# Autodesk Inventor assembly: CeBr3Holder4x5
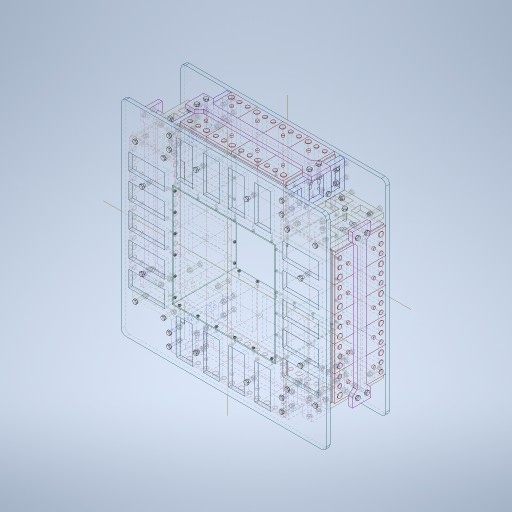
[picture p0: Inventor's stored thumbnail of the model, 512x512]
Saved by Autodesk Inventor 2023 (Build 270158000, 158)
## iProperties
Created: 2023-10
Part Number: CeBr3Holder4x5
Document SubType Name: Assembly
Designer: tornqvih
Mass: 42931.8 g
Surface Area: 23628.1 cm^2
Volume: 15849 cm^3
Density: 2.7088 g/cm^3
Author: tornqvih
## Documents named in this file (21)
- \\Mac\Home\Documents\chalmers\Inventor2023\CeBr3Holder4x5\CeBr3Holder4x5.iam
- \\Mac\Home\Documents\chalmers\Inventor2023\CeBr3Holder4x5\FrontPlate.ipt
- \\Mac\Home\Documents\chalmers\Inventor2023\CeBr3Holder4x5\ShieldTop.ipt
- \\Mac\Home\Documents\chalmers\Inventor2023\CeBr3Holder4x5\ShieldLeft.ipt
- \\Mac\Home\Documents\chalmers\Inventor2023\CeBr3Holder4x5\SupportHorizontal.ipt
- \\Mac\Home\Documents\chalmers\Inventor2023\CeBr3Holder4x5\SupportVertical.ipt
- \\Mac\Home\Documents\chalmers\Inventor2023\CeBr3Holder4x5\BarHorizontal.ipt
- \\Mac\Home\Documents\chalmers\Inventor2023\CeBr3Holder4x5\BarVertical.ipt
- \\Mac\Home\Documents\chalmers\Inventor2023\CeBr3Holder4x5\CeBr3.ipt
- \\Mac\Home\Documents\Inventor\Content Center Files\R2023\en-US\AS 1110\AS 1110 - M5 x 25.ipt
- \\Mac\Home\Documents\Inventor\Content Center Files\R2023\en-US\AS 1112 (2)\AS 1112 - M5  Type 5.ipt
- \\Mac\Home\Documents\Inventor\Content Center Files\R2023\en-US\AS 1427(05)\AS 1427 - M2.5 x 8(5) II.ipt
- \\Mac\Home\Documents\Inventor\Content Center Files\R2023\en-US\AS 1110\AS 1110 - M5 x 35.ipt
- \\Mac\Home\Documents\Inventor\Content Center Files\R2023\en-US\AS 1110\AS 1110 - M5 x 40.ipt
- \\Mac\Home\Documents\Inventor\Content Center Files\R2023\en-US\ANSI B18.2.4.2M\ANSI B18.2.4.2M - M5x0.8 - 8.ipt
- \\Mac\Home\Documents\chalmers\Inventor2023\CeBr3Holder4x5\Mount.ipt
- \\Mac\Home\Documents\chalmers\Inventor2023\CeBr3Holder4x5\PressTopBottom.ipt
- \\Mac\Home\Documents\chalmers\Inventor2023\CeBr3Holder4x5\PressRightLeft.ipt
- \\Mac\Home\Documents\chalmers\Inventor2023\CeBr3Holder4x5\PressSide.ipt
- \\Mac\Home\Documents\Inventor\Content Center Files\R2023\en-US\AS 1474(1)\AS 1474 - M5(1).ipt
- \\Mac\Home\Documents\Inventor\Content Center Files\R2023\en-US\AS 1110\AS 1110 - M5 x 20.ipt
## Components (239 placed, 36 different names)
1. FrontPlate
2. BackPlate
3. ShieldTop
4. ShieldBottom
5. ShieldLeft
6. ShieldRight
7. SupportHorizontalTR
8. SupportHorizontalTL
9. SupportHorizontalBL
10. SupportHorizontalBR
11. SupportVerticalTR
12. SupportVerticalTL
13. SupportVerticalBL
14. SupportVerticalBR
15. BarHorizontalTop — Mate:129, Mate:131, Flush:129
16. BarHorizontalBottom — Mate:132, Mate:133, Flush:130
17. BarVerticalRight — Mate:134, Mate:135, Flush:131
18. BarVertical:2 — Mate:136, Mate:137, Flush:132
19. CeBr3:1 — Mate:138, Mate:139, Mate:140, Mate:143, Mate:151
20. CeBr3:2 — Mate:141, Mate:142, Mate:143, Mate:146, Mate:154
21. CeBr3:3 — Mate:144, Mate:145, Mate:146, Mate:149, Mate:157
22. CeBr3:4 — Mate:147, Mate:148, Mate:149, Mate:160, Mate:269
23. CeBr3:5 — Mate:150, Mate:151, Mate:152, Mate:155, Mate:257, Mate:277
24. CeBr3:6 — Mate:153, Mate:154, Mate:155, Mate:158
25. CeBr3:7 — Mate:156, Mate:157, Mate:158, Mate:161
26. CeBr3:8 — Mate:159, Mate:160, Mate:161
27. CeBr3:9 — Mate:162, Mate:163, Mate:164, Mate:167, Mate:175
28. CeBr3:10 — Mate:165, Mate:166, Mate:167, Mate:170, Mate:178
29. CeBr3:11 — Mate:168, Mate:169, Mate:170, Mate:173, Mate:181
30. CeBr3:12 — Mate:171, Mate:172, Mate:173, Mate:184, Mate:272
31. CeBr3:13 — Mate:174, Mate:175, Mate:176, Mate:179, Mate:260
32. CeBr3:14 — Mate:177, Mate:178, Mate:179, Mate:182
33. CeBr3:15 — Mate:180, Mate:181, Mate:182, Mate:185
34. CeBr3:16 — Mate:183, Mate:184, Mate:185
35. CeBr3:17 — Mate:186, Mate:187, Mate:188, Mate:191, Mate:202
36. CeBr3:18 — Mate:189, Mate:190, Mate:191, Mate:194, Mate:205
37. CeBr3:19 — Mate:192, Mate:193, Mate:194, Mate:197, Mate:208
38. CeBr3:20 — Mate:195, Mate:196, Mate:197, Mate:200, Mate:211
39. CeBr3:21 — Mate:198, Mate:199, Mate:200, Mate:214, Mate:278
40. CeBr3:22 — Mate:201, Mate:202, Mate:203, Mate:206, Mate:266
41. CeBr3:23 — Mate:204, Mate:205, Mate:206, Mate:209
42. CeBr3:24 — Mate:207, Mate:208, Mate:209, Mate:212
43. CeBr3:25 — Mate:210, Mate:211, Mate:212, Mate:215
44. CeBr3:26 — Mate:213, Mate:214, Mate:215
45. CeBr3:27 — Mate:216, Mate:217, Mate:218, Mate:221, Mate:232
46. CeBr3:28 — Mate:219, Mate:220, Mate:221, Mate:224, Mate:235
47. CeBr3:29 — Mate:222, Mate:223, Mate:224, Mate:227, Mate:238
48. CeBr3:30 — Mate:225, Mate:226, Mate:227, Mate:230, Mate:241
49. CeBr3:31 — Mate:228, Mate:229, Mate:230, Mate:244, Mate:275
50. CeBr3:32 — Mate:231, Mate:232, Mate:233, Mate:236, Mate:263
51. CeBr3:33 — Mate:234, Mate:235, Mate:236, Mate:239
52. CeBr3:34 — Mate:237, Mate:238, Mate:239, Mate:242
53. CeBr3:35 — Mate:240, Mate:241, Mate:242, Mate:245
54. CeBr3:36 — Mate:243, Mate:244, Mate:245
55. AS 1110 - Metric M5 x 25:1
56. AS 1110 - Metric M5 x 25:2
57. AS 1110 - Metric M5 x 25:3
58. AS 1110 - Metric M5 x 25:4
59. AS 1110 - Metric M5 x 25:5
60. AS 1110 - Metric M5 x 25:6
61. AS 1110 - Metric M5 x 25:7
62. AS 1110 - Metric M5 x 25:8
63. AS 1110 - Metric M5 x 25:9
64. AS 1110 - Metric M5 x 25:10
65. AS 1110 - Metric M5 x 25:11
66. AS 1110 - Metric M5 x 25:12
67. AS 1110 - Metric M5 x 25:13
68. AS 1110 - Metric M5 x 25:14
69. AS 1110 - Metric M5 x 25:15
70. AS 1110 - Metric M5 x 25:16
71. AS 1110 - Metric M5 x 25:17
72. AS 1110 - Metric M5 x 25:18
73. AS 1110 - Metric M5 x 25:19
74. AS 1110 - Metric M5 x 25:20
75. AS 1110 - Metric M5 x 25:21
76. AS 1110 - Metric M5 x 25:22
77. AS 1110 - Metric M5 x 25:23
78. AS 1110 - Metric M5 x 25:24
79. AS 1110 - Metric M5 x 25:25
80. AS 1110 - Metric M5 x 25:26
81. AS 1110 - Metric M5 x 25:27
82. AS 1110 - Metric M5 x 25:28
83. AS 1110 - Metric M5 x 25:29
84. AS 1110 - Metric M5 x 25:30
85. AS 1110 - Metric M5 x 25:31
86. AS 1110 - Metric M5 x 25:32
87. AS 1112 (2) - Metric M5  Type 5:1
88. AS 1112 (2) - Metric M5  Type 5:2
89. AS 1112 (2) - Metric M5  Type 5:3
90. AS 1112 (2) - Metric M5  Type 5:4
91. AS 1112 (2) - Metric M5  Type 5:5
92. AS 1112 (2) - Metric M5  Type 5:6
93. AS 1112 (2) - Metric M5  Type 5:7
94. AS 1112 (2) - Metric M5  Type 5:8
95. AS 1112 (2) - Metric M5  Type 5:9
96. AS 1112 (2) - Metric M5  Type 5:10
97. AS 1112 (2) - Metric M5  Type 5:11
98. AS 1112 (2) - Metric M5  Type 5:12
99. AS 1112 (2) - Metric M5  Type 5:13
100. AS 1112 (2) - Metric M5  Type 5:14
101. AS 1112 (2) - Metric M5  Type 5:15
102. AS 1112 (2) - Metric M5  Type 5:16
103. AS 1112 (2) - Metric M5  Type 5:17
104. AS 1112 (2) - Metric M5  Type 5:18
105. AS 1112 (2) - Metric M5  Type 5:19
106. AS 1112 (2) - Metric M5  Type 5:20
107. AS 1112 (2) - Metric M5  Type 5:21
108. AS 1112 (2) - Metric M5  Type 5:22
109. AS 1112 (2) - Metric M5  Type 5:23
110. AS 1112 (2) - Metric M5  Type 5:24
111. AS 1112 (2) - Metric M5  Type 5:25
112. AS 1112 (2) - Metric M5  Type 5:26
113. AS 1112 (2) - Metric M5  Type 5:27
114. AS 1112 (2) - Metric M5  Type 5:28
115. AS 1112 (2) - Metric M5  Type 5:29
116. AS 1112 (2) - Metric M5  Type 5:30
117. AS 1112 (2) - Metric M5  Type 5:31
118. AS 1112 (2) - Metric M5  Type 5:32
119. AS 1427 H - Metric M2.5 x 8:1
120. AS 1427 H - Metric M2.5 x 8:2
121. AS 1427 H - Metric M2.5 x 8:3
122. AS 1427 H - Metric M2.5 x 8:4
123. AS 1427 H - Metric M2.5 x 8:5
124. AS 1427 H - Metric M2.5 x 8:6
125. AS 1427 H - Metric M2.5 x 8:7
126. AS 1427 H - Metric M2.5 x 8:8
127. AS 1427 H - Metric M2.5 x 8:9
128. AS 1427 H - Metric M2.5 x 8:10
129. AS 1427 H - Metric M2.5 x 8:11
130. AS 1427 H - Metric M2.5 x 8:12
131. AS 1427 H - Metric M2.5 x 8:13
132. AS 1427 H - Metric M2.5 x 8:14
133. AS 1427 H - Metric M2.5 x 8:15
134. AS 1427 H - Metric M2.5 x 8:16
135. AS 1427 H - Metric M2.5 x 8:17
136. AS 1427 H - Metric M2.5 x 8:18
137. AS 1427 H - Metric M2.5 x 8:19
138. AS 1427 H - Metric M2.5 x 8:20
139. AS 1427 H - Metric M2.5 x 8:21
140. AS 1427 H - Metric M2.5 x 8:22
141. AS 1427 H - Metric M2.5 x 8:23
142. AS 1427 H - Metric M2.5 x 8:24
143. AS 1427 H - Metric M2.5 x 8:25
144. AS 1427 H - Metric M2.5 x 8:26
145. AS 1427 H - Metric M2.5 x 8:27
146. AS 1427 H - Metric M2.5 x 8:28
147. AS 1427 H - Metric M2.5 x 8:29
148. AS 1427 H - Metric M2.5 x 8:30
149. AS 1427 H - Metric M2.5 x 8:31
150. AS 1427 H - Metric M2.5 x 8:32
151. AS 1427 H - Metric M2.5 x 8:33
152. AS 1427 H - Metric M2.5 x 8:34
153. AS 1427 H - Metric M2.5 x 8:35
154. AS 1427 H - Metric M2.5 x 8:36
155. AS 1427 H - Metric M2.5 x 8:37
156. AS 1427 H - Metric M2.5 x 8:38
157. AS 1427 H - Metric M2.5 x 8:39
158. AS 1427 H - Metric M2.5 x 8:40
159. AS 1427 H - Metric M2.5 x 8:41
160. AS 1427 H - Metric M2.5 x 8:42
161. AS 1427 H - Metric M2.5 x 8:43
162. AS 1427 H - Metric M2.5 x 8:44
163. AS 1427 H - Metric M2.5 x 8:45
164. AS 1427 H - Metric M2.5 x 8:46
165. AS 1427 H - Metric M2.5 x 8:47
166. AS 1427 H - Metric M2.5 x 8:48
167. AS 1110 - Metric M5 x 35:25
168. AS 1110 - Metric M5 x 35:3
169. AS 1110 - Metric M5 x 35:5
170. AS 1110 - Metric M5 x 35:6
171. AS 1110 - Metric M5 x 35:7
172. AS 1110 - Metric M5 x 35:9
173. AS 1110 - Metric M5 x 35:11
174. AS 1110 - Metric M5 x 35:12
175. AS 1110 - Metric M5 x 35:13
176. AS 1110 - Metric M5 x 35:15
177. AS 1110 - Metric M5 x 35:16
178. AS 1110 - Metric M5 x 35:18
179. AS 1110 - Metric M5 x 40:1
180. AS 1110 - Metric M5 x 40:3
181. AS 1110 - Metric M5 x 40:4
182. AS 1110 - Metric M5 x 40:6
183. ANSI B18.2.4.2M M5x0.8:1
184. ANSI B18.2.4.2M M5x0.8:3
185. ANSI B18.2.4.2M M5x0.8:4
186. ANSI B18.2.4.2M M5x0.8:6
187. ANSI B18.2.4.2M M5x0.8:7
188. ANSI B18.2.4.2M M5x0.8:9
189. ANSI B18.2.4.2M M5x0.8:10
190. ANSI B18.2.4.2M M5x0.8:12
191. ANSI B18.2.4.2M M5x0.8:13
192. ANSI B18.2.4.2M M5x0.8:15
193. ANSI B18.2.4.2M M5x0.8:16
194. ANSI B18.2.4.2M M5x0.8:18
195. ANSI B18.2.4.2M M5x0.8:19
196. ANSI B18.2.4.2M M5x0.8:21
197. ANSI B18.2.4.2M M5x0.8:22
198. ANSI B18.2.4.2M M5x0.8:24
199. Mount:1 — Mate:255
200. PressTop — Mate:256, Mate:257, Mate:258, Mate:280, Mate:282
201. PressBottom — Mate:259, Mate:260, Mate:261, Mate:288, Mate:290
202. PressRight — Mate:262, Mate:263, Mate:264, Mate:284, Mate:286
203. PressLef — Mate:265, Mate:266, Mate:267, Mate:292, Mate:294
204. PressSideTop — Mate:268, Mate:269, Mate:270, Mate:274, Mate:296, Mate:298
205. PressSideBottom — Mate:271, Mate:272, Mate:273, Mate:304, Mate:306
206. PressSideRight — Mate:274, Mate:275, Mate:276, Mate:300, Mate:302
207. PressSideLeft — Mate:277, Mate:278, Mate:279, Mate:308, Mate:310
208. AS 1474 - Metric M5:1
209. AS 1474 - Metric M5:2
210. AS 1474 - Metric M5:3
211. AS 1474 - Metric M5:4
212. AS 1474 - Metric M5:5
213. AS 1474 - Metric M5:6
214. AS 1474 - Metric M5:7
215. AS 1474 - Metric M5:8
216. AS 1474 - Metric M5:9
217. AS 1474 - Metric M5:10
218. AS 1474 - Metric M5:11
219. AS 1474 - Metric M5:12
220. AS 1474 - Metric M5:13
221. AS 1474 - Metric M5:14
222. AS 1474 - Metric M5:15
223. AS 1474 - Metric M5:16
224. AS 1110 - Metric M5 x 20:33 — Mate:280, Mate:281
225. AS 1110 - Metric M5 x 20:2 — Mate:282, Mate:283
226. AS 1110 - Metric M5 x 20:3 — Mate:284, Mate:285
227. AS 1110 - Metric M5 x 20:4 — Mate:286, Mate:287
228. AS 1110 - Metric M5 x 20:5 — Mate:288, Mate:289
229. AS 1110 - Metric M5 x 20:6 — Mate:290, Mate:291
230. AS 1110 - Metric M5 x 20:7 — Mate:292, Mate:293
231. AS 1110 - Metric M5 x 20:8 — Mate:294, Mate:295
232. AS 1110 - Metric M5 x 20:9 — Mate:296, Mate:297
233. AS 1110 - Metric M5 x 20:10 — Mate:298, Mate:299
234. AS 1110 - Metric M5 x 20:11 — Mate:300, Mate:301
235. AS 1110 - Metric M5 x 20:12 — Mate:302, Mate:303
236. AS 1110 - Metric M5 x 20:13 — Mate:304, Mate:305
237. AS 1110 - Metric M5 x 20:14 — Mate:306, Mate:307
238. AS 1110 - Metric M5 x 20:15 — Mate:308, Mate:309
239. AS 1110 - Metric M5 x 20:16 — Mate:310, Mate:311
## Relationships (177: Mate 173, Flush 4)
- Mate:129: BarHorizontalTop
- Mate:131: BarHorizontalTop
- Flush:129: BarHorizontalTop
- Mate:132: BarHorizontalBottom
- Mate:133: BarHorizontalBottom
- Flush:130: BarHorizontalBottom
- Mate:134: BarVerticalRight
- Mate:135: BarVerticalRight
- Flush:131: BarVerticalRight
- Mate:136: BarVertical:2
- Mate:137: BarVertical:2
- Flush:132: BarVertical:2
- Mate:138: CeBr3:1
- Mate:139: CeBr3:1
- Mate:140: CeBr3:1
- Mate:141: CeBr3:2
- Mate:142: CeBr3:2
- Mate:143: CeBr3:1 ↔ CeBr3:2
- Mate:144: CeBr3:3
- Mate:145: CeBr3:3
- Mate:146: CeBr3:2 ↔ CeBr3:3
- Mate:147: CeBr3:4
- Mate:148: CeBr3:4
- Mate:149: CeBr3:3 ↔ CeBr3:4
- Mate:150: CeBr3:5
- Mate:151: CeBr3:1 ↔ CeBr3:5
- Mate:152: CeBr3:5
- Mate:153: CeBr3:6
- Mate:154: CeBr3:2 ↔ CeBr3:6
- Mate:155: CeBr3:5 ↔ CeBr3:6
- Mate:156: CeBr3:7
- Mate:157: CeBr3:3 ↔ CeBr3:7
- Mate:158: CeBr3:6 ↔ CeBr3:7
- Mate:159: CeBr3:8
- Mate:160: CeBr3:4 ↔ CeBr3:8
- Mate:161: CeBr3:7 ↔ CeBr3:8
- Mate:162: CeBr3:9
- Mate:163: CeBr3:9
- Mate:164: CeBr3:9
- Mate:165: CeBr3:10
- Mate:166: CeBr3:10
- Mate:167: CeBr3:9 ↔ CeBr3:10
- Mate:168: CeBr3:11
- Mate:169: CeBr3:11
- Mate:170: CeBr3:10 ↔ CeBr3:11
- Mate:171: CeBr3:12
- Mate:172: CeBr3:12
- Mate:173: CeBr3:11 ↔ CeBr3:12
- Mate:174: CeBr3:13
- Mate:175: CeBr3:9 ↔ CeBr3:13
- Mate:176: CeBr3:13
- Mate:177: CeBr3:14
- Mate:178: CeBr3:10 ↔ CeBr3:14
- Mate:179: CeBr3:13 ↔ CeBr3:14
- Mate:180: CeBr3:15
- Mate:181: CeBr3:11 ↔ CeBr3:15
- Mate:182: CeBr3:14 ↔ CeBr3:15
- Mate:183: CeBr3:16
- Mate:184: CeBr3:12 ↔ CeBr3:16
- Mate:185: CeBr3:15 ↔ CeBr3:16
- Mate:186: CeBr3:17
- Mate:187: CeBr3:17
- Mate:188: CeBr3:17
- Mate:189: CeBr3:18
- Mate:190: CeBr3:18
- Mate:191: CeBr3:17 ↔ CeBr3:18
- Mate:192: CeBr3:19
- Mate:193: CeBr3:19
- Mate:194: CeBr3:18 ↔ CeBr3:19
- Mate:195: CeBr3:20
- Mate:196: CeBr3:20
- Mate:197: CeBr3:19 ↔ CeBr3:20
- Mate:198: CeBr3:21
- Mate:199: CeBr3:21
- Mate:200: CeBr3:20 ↔ CeBr3:21
- Mate:201: CeBr3:22
- Mate:202: CeBr3:17 ↔ CeBr3:22
- Mate:203: CeBr3:22
- Mate:204: CeBr3:23
- Mate:205: CeBr3:18 ↔ CeBr3:23
- Mate:206: CeBr3:22 ↔ CeBr3:23
- Mate:207: CeBr3:24
- Mate:208: CeBr3:19 ↔ CeBr3:24
- Mate:209: CeBr3:23 ↔ CeBr3:24
- Mate:210: CeBr3:25
- Mate:211: CeBr3:20 ↔ CeBr3:25
- Mate:212: CeBr3:24 ↔ CeBr3:25
- Mate:213: CeBr3:26
- Mate:214: CeBr3:21 ↔ CeBr3:26
- Mate:215: CeBr3:25 ↔ CeBr3:26
- Mate:216: CeBr3:27
- Mate:217: CeBr3:27
- Mate:218: CeBr3:27
- Mate:219: CeBr3:28
- Mate:220: CeBr3:28
- Mate:221: CeBr3:27 ↔ CeBr3:28
- Mate:222: CeBr3:29
- Mate:223: CeBr3:29
- Mate:224: CeBr3:28 ↔ CeBr3:29
- Mate:225: CeBr3:30
- Mate:226: CeBr3:30
- Mate:227: CeBr3:29 ↔ CeBr3:30
- Mate:228: CeBr3:31
- Mate:229: CeBr3:31
- Mate:230: CeBr3:30 ↔ CeBr3:31
- Mate:231: CeBr3:32
- Mate:232: CeBr3:27 ↔ CeBr3:32
- Mate:233: CeBr3:32
- Mate:234: CeBr3:33
- Mate:235: CeBr3:28 ↔ CeBr3:33
- Mate:236: CeBr3:32 ↔ CeBr3:33
- Mate:237: CeBr3:34
- Mate:238: CeBr3:29 ↔ CeBr3:34
- Mate:239: CeBr3:33 ↔ CeBr3:34
- Mate:240: CeBr3:35
- Mate:241: CeBr3:30 ↔ CeBr3:35
- Mate:242: CeBr3:34 ↔ CeBr3:35
- Mate:243: CeBr3:36
- Mate:244: CeBr3:31 ↔ CeBr3:36
- Mate:245: CeBr3:35 ↔ CeBr3:36
- Mate:255: Mount:1
- Mate:256: PressTop
- Mate:257: CeBr3:5 ↔ PressTop
- Mate:258: PressTop
- Mate:259: PressBottom
- Mate:260: CeBr3:13 ↔ PressBottom
- Mate:261: PressBottom
- Mate:262: PressRight
- Mate:263: CeBr3:32 ↔ PressRight
- Mate:264: PressRight
- Mate:265: PressLef
- Mate:266: CeBr3:22 ↔ PressLef
- Mate:267: PressLef
- Mate:268: PressSideTop
- Mate:269: CeBr3:4 ↔ PressSideTop
- Mate:270: PressSideTop
- Mate:271: PressSideBottom
- Mate:272: CeBr3:12 ↔ PressSideBottom
- Mate:273: PressSideBottom
- Mate:274: PressSideTop ↔ PressSideRight
- Mate:275: CeBr3:31 ↔ PressSideRight
- Mate:276: PressSideRight
- Mate:277: CeBr3:5 ↔ PressSideLeft
- Mate:278: CeBr3:21 ↔ PressSideLeft
- Mate:279: PressSideLeft
- Mate:280: PressTop ↔ AS 1110 - Metric M5 x 20:33
- Mate:281: AS 1110 - Metric M5 x 20:33
- Mate:282: PressTop ↔ AS 1110 - Metric M5 x 20:2
- Mate:283: AS 1110 - Metric M5 x 20:2
- Mate:284: PressRight ↔ AS 1110 - Metric M5 x 20:3
- Mate:285: AS 1110 - Metric M5 x 20:3
- Mate:286: PressRight ↔ AS 1110 - Metric M5 x 20:4
- Mate:287: AS 1110 - Metric M5 x 20:4
- Mate:288: PressBottom ↔ AS 1110 - Metric M5 x 20:5
- Mate:289: AS 1110 - Metric M5 x 20:5
- Mate:290: PressBottom ↔ AS 1110 - Metric M5 x 20:6
- Mate:291: AS 1110 - Metric M5 x 20:6
- Mate:292: PressLef ↔ AS 1110 - Metric M5 x 20:7
- Mate:293: AS 1110 - Metric M5 x 20:7
- Mate:294: PressLef ↔ AS 1110 - Metric M5 x 20:8
- Mate:295: AS 1110 - Metric M5 x 20:8
- Mate:296: PressSideTop ↔ AS 1110 - Metric M5 x 20:9
- Mate:297: AS 1110 - Metric M5 x 20:9
- Mate:298: PressSideTop ↔ AS 1110 - Metric M5 x 20:10
- Mate:299: AS 1110 - Metric M5 x 20:10
- Mate:300: PressSideRight ↔ AS 1110 - Metric M5 x 20:11
- Mate:301: AS 1110 - Metric M5 x 20:11
- Mate:302: PressSideRight ↔ AS 1110 - Metric M5 x 20:12
- Mate:303: AS 1110 - Metric M5 x 20:12
- Mate:304: PressSideBottom ↔ AS 1110 - Metric M5 x 20:13
- Mate:305: AS 1110 - Metric M5 x 20:13
- Mate:306: PressSideBottom ↔ AS 1110 - Metric M5 x 20:14
- Mate:307: AS 1110 - Metric M5 x 20:14
- Mate:308: PressSideLeft ↔ AS 1110 - Metric M5 x 20:15
- Mate:309: AS 1110 - Metric M5 x 20:15
- Mate:310: PressSideLeft ↔ AS 1110 - Metric M5 x 20:16
- Mate:311: AS 1110 - Metric M5 x 20:16
## Named parameters: sa_0 = 0 mm, sa_2 = 0
